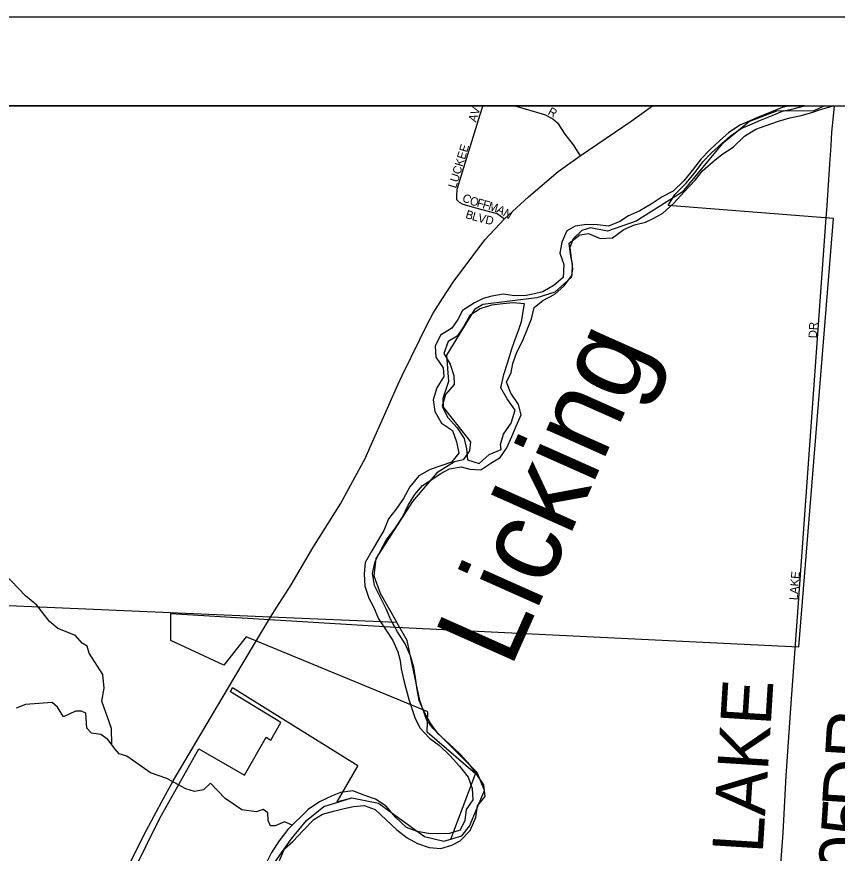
# Model space of a CAD drawing. Extents: x 0 to 40.4, y 0 to 22.
# Drawn here: x 7.886 to 8.807, y 20.061 to 21 of the extents above; entities that cross this region are included whole.
import ezdxf

# ---------------------------------------------------------------- set-up
doc = ezdxf.new("R2010")
doc.units = 0
for name, color, linetype in [('GM_X_City_Street', 7, 'Continuous'), ('GM_X_City_Street_Text', 7, 'Continuous'), ('GM_X_Corporation', 7, 'Continuous'), ('GM_X_County_Road', 7, 'Continuous'), ('GM_X_County_Road_Text', 7, 'Continuous'), ('GM_X_Major_River', 7, 'Continuous'), ('GM_X_Major_River_Text', 7, 'Continuous'), ('GM_X_Minor_River', 7, 'Continuous'), ('GM_X_State_Route', 7, 'Continuous'), ('GM_X_Township', 7, 'Continuous'), ('SH_Data', 7, 'Continuous')]:
    doc.layers.add(name, color=color, linetype=linetype)

msp = doc.modelspace()

# ---------------------------------------------------------------- linework, layer by layer
at = {"layer": 'GM_X_City_Street'}
for points in [[(8.3832, 20.7918), (8.38037, 20.79441), (8.38037, 20.79871), (8.38085, 20.80635), (8.40483, 20.88421), (8.40931, 20.89865), (8.40988, 20.9)], [(8.44554, 20.9), (8.47862, 20.8903), (8.48816, 20.88552), (8.49325, 20.88075), (8.50151, 20.86835), (8.51105, 20.85626), (8.51888, 20.84366)], [(8.3832, 20.7918), (8.38733, 20.78947), (8.40689, 20.78389), (8.42552, 20.77911), (8.43389, 20.77314)], [(8.76279, 20.32617), (8.79491, 20.77428), (8.79587, 20.78799)]]:
    msp.add_lwpolyline(points, dxfattribs=at)
at = {"layer": 'GM_X_Corporation'}
msp.add_line((8.77111, 20.9), (7.12768, 20.9), dxfattribs=at)
msp.add_lwpolyline([(7.92261, 19.84799), (8.04698, 20.10032), (8.09082, 20.17826), (8.14193, 20.14846), (8.16655, 20.19111), (8.17153, 20.188), (8.18298, 20.20784), (8.12643, 20.24202), (8.12866, 20.24682), (8.26913, 20.15958), (8.24575, 20.11864), (8.26251, 20.12298), (8.29252, 20.11699), (8.3443, 20.07961), (8.36594, 20.07446), (8.37365, 20.0767), (8.40118, 20.15007), (8.34715, 20.19685), (8.34786, 20.21962), (8.14411, 20.30392), (8.11903, 20.27206), (8.05953, 20.29981), (8.05953, 20.3301), (8.31154, 20.31467), (8.7642, 20.29247), (8.80299, 20.77365), (8.61749, 20.7881), (8.62503, 20.80048), (8.63741, 20.81279), (8.6471, 20.82437), (8.6569, 20.8375), (8.66611, 20.84703), (8.67779, 20.85753), (8.68707, 20.86603), (8.69941, 20.87434), (8.71196, 20.87985), (8.7214, 20.88397), (8.73425, 20.88923), (8.74605, 20.894), (8.75792, 20.89657), (8.77072, 20.89993), (8.77111, 20.9)], dxfattribs=at)
at = {"layer": 'GM_X_County_Road'}
for points in [[(8.79587, 20.78799), (8.79912, 20.83448), (8.80043, 20.85541), (8.80141, 20.87044), (8.80305, 20.88842), (8.80434, 20.9)], [(8.7332, 19.87386), (8.73264, 19.88464), (8.73362, 19.90129), (8.73684, 19.94579), (8.74104, 20.00863), (8.74663, 20.08391), (8.74999, 20.14786), (8.75545, 20.22385), (8.76279, 20.32617)]]:
    msp.add_lwpolyline(points, dxfattribs=at)
at = {"layer": 'GM_X_Major_River'}
for points in [[(8.75354, 20.9), (8.74557, 20.89827), (8.73343, 20.89337), (8.72053, 20.88809), (8.71104, 20.88394), (8.69815, 20.87828), (8.68524, 20.86959), (8.67574, 20.86089), (8.66397, 20.85031), (8.65447, 20.84048), (8.64458, 20.82724), (8.63508, 20.81589), (8.62331, 20.80417), (8.61078, 20.79775), (8.59864, 20.78944), (8.58573, 20.78226), (8.57321, 20.77661), (8.56334, 20.77018), (8.55082, 20.7649), (8.53832, 20.76644), (8.52581, 20.76684), (8.5133, 20.76497), (8.50382, 20.75968), (8.4981, 20.74681), (8.49617, 20.73469), (8.50069, 20.72181), (8.4999, 20.70741), (8.48965, 20.69872)], [(8.51017, 20.72217), (8.50792, 20.73354), (8.50643, 20.74566), (8.51858, 20.75511), (8.52806, 20.75661), (8.54131, 20.7509), (8.55496, 20.75164), (8.56787, 20.76108), (8.57963, 20.76636), (8.59215, 20.76937), (8.60163, 20.7739), (8.6115, 20.77957), (8.62365, 20.79015), (8.63543, 20.80339), (8.64797, 20.81662), (8.65595, 20.82684), (8.66811, 20.83742), (8.67798, 20.84536), (8.69051, 20.85367), (8.70342, 20.86577), (8.71595, 20.8737), (8.72657, 20.87747), (8.74136, 20.88275), (8.75426, 20.88651), (8.76677, 20.88914), (8.77891, 20.89253), (8.78839, 20.89592), (8.80166, 20.89969), (8.80442, 20.9)], [(8.1815, 20.05264), (8.18683, 20.06589), (8.19633, 20.0742), (8.20849, 20.08668), (8.21989, 20.09878), (8.22975, 20.10483), (8.24189, 20.10821), (8.25402, 20.11122), (8.26426, 20.11348), (8.27639, 20.11459), (8.28889, 20.11002), (8.30099, 20.09826), (8.31309, 20.08725), (8.32482, 20.07814), (8.33617, 20.07168), (8.34943, 20.06748), (8.36231, 20.06632), (8.37483, 20.07009), (8.38431, 20.075), (8.39533, 20.08634), (8.40181, 20.1011), (8.40374, 20.11398), (8.4121, 20.12457), (8.41061, 20.13783), (8.40193, 20.15035), (8.39551, 20.15983), (8.38454, 20.17159), (8.37131, 20.18412), (8.35959, 20.19513), (8.3509, 20.20689), (8.3441, 20.21902), (8.33807, 20.23229), (8.33583, 20.24479), (8.33396, 20.25768), (8.3321, 20.2698), (8.32834, 20.28269), (8.3223, 20.29596), (8.314, 20.30961), (8.30645, 20.32289), (8.30118, 20.3354), (8.29438, 20.34867), (8.28797, 20.36156), (8.28573, 20.37482), (8.28879, 20.38845), (8.29565, 20.40208), (8.30098, 20.4123), (8.31086, 20.42516), (8.31961, 20.43802), (8.32571, 20.45165), (8.33332, 20.46376), (8.34206, 20.47359), (8.35231, 20.48039), (8.3618, 20.48681), (8.37204, 20.49248), (8.38531, 20.49473), (8.39516, 20.49206), (8.40729, 20.49128), (8.41868, 20.49883), (8.42892, 20.50525), (8.43653, 20.51622), (8.44225, 20.52871), (8.44682, 20.54045), (8.45254, 20.55294), (8.44953, 20.56469), (8.44085, 20.57759), (8.43633, 20.58972), (8.44128, 20.60069), (8.4432, 20.61054), (8.44778, 20.62341), (8.45425, 20.6359), (8.45959, 20.64953), (8.46416, 20.66088), (8.46722, 20.67376), (8.4771, 20.68132), (8.49038, 20.68849), (8.50063, 20.69756), (8.50976, 20.71005), (8.51017, 20.72217)], [(8.48965, 20.69872), (8.47712, 20.69117), (8.46764, 20.68891), (8.45816, 20.68703), (8.44527, 20.68668), (8.43239, 20.6886), (8.41988, 20.68635), (8.41002, 20.68371), (8.40015, 20.6788), (8.38687, 20.67011), (8.38154, 20.66028), (8.37469, 20.65044), (8.36217, 20.64251), (8.35607, 20.63002), (8.3568, 20.61789), (8.36511, 20.60576), (8.36585, 20.59628), (8.35786, 20.58342), (8.35404, 20.56979), (8.3559, 20.55691), (8.36307, 20.54363), (8.37556, 20.53566), (8.38008, 20.52277), (8.3827, 20.50988), (8.37434, 20.50005), (8.36258, 20.4959), (8.35044, 20.49176), (8.33791, 20.48458), (8.32765, 20.4721), (8.32042, 20.45923), (8.31205, 20.44675), (8.30369, 20.43616), (8.29835, 20.42329), (8.2915, 20.41118), (8.28503, 20.40058), (8.27742, 20.38734), (8.27625, 20.37446), (8.27698, 20.36082), (8.2815, 20.34718), (8.28678, 20.3377), (8.29243, 20.32405), (8.30074, 20.31153), (8.30867, 20.29977), (8.31433, 20.28688), (8.31696, 20.27741), (8.31807, 20.26793), (8.32069, 20.25619), (8.32333, 20.24633), (8.32708, 20.23231), (8.3331, 20.21336), (8.33876, 20.20161), (8.34972, 20.19022), (8.36107, 20.18187), (8.37279, 20.1701), (8.38338, 20.15872), (8.3932, 20.1462), (8.39772, 20.13369), (8.39845, 20.12081), (8.39084, 20.10984), (8.3893, 20.09772), (8.38434, 20.08674), (8.37221, 20.08297), (8.35856, 20.08262), (8.34871, 20.08302), (8.33583, 20.08531), (8.32409, 20.08988), (8.31161, 20.10127), (8.30103, 20.11379), (8.2893, 20.12176), (8.27718, 20.12557), (8.26354, 20.1309), (8.2499, 20.12903), (8.24041, 20.12526), (8.22637, 20.11847), (8.21347, 20.11016), (8.19068, 20.08747), (8.18117, 20.07499), (8.17242, 20.06175), (8.16633, 20.04964)], [(8.45624, 20.67757), (8.44374, 20.67872), (8.43199, 20.67761), (8.41948, 20.67612), (8.40658, 20.67197), (8.39519, 20.66442), (8.38796, 20.65193), (8.38074, 20.64134), (8.37087, 20.63529), (8.36591, 20.62204), (8.37308, 20.60991), (8.37722, 20.5974), (8.37758, 20.58717), (8.36769, 20.57582), (8.36387, 20.56295), (8.36991, 20.55044), (8.38087, 20.5383), (8.3888, 20.52654), (8.39143, 20.51479), (8.39253, 20.50267), (8.40541, 20.49848), (8.4168, 20.50868), (8.43008, 20.51434)], [(8.43008, 20.51434), (8.42934, 20.51965), (8.43278, 20.53139), (8.44152, 20.54387), (8.44573, 20.55826), (8.43704, 20.57115), (8.42987, 20.58329), (8.43332, 20.59843), (8.43752, 20.61206), (8.44172, 20.62607), (8.44515, 20.63592), (8.44973, 20.64765), (8.45316, 20.65787), (8.45624, 20.67757)]]:
    msp.add_lwpolyline(points, dxfattribs=at)
at = {"layer": 'GM_X_Minor_River'}
for points in [[(7.99318, 20.18271), (7.99297, 20.20087), (7.98194, 20.23156), (7.98458, 20.24635), (7.98305, 20.26151), (7.96787, 20.28537), (7.96559, 20.29333), (7.9599, 20.29673), (7.95231, 20.30544), (7.93259, 20.31338), (7.92311, 20.32095), (7.90907, 20.33951), (7.89618, 20.34973), (7.87227, 20.3751)], [(8.19569, 20.09246), (8.18711, 20.0961), (8.1765, 20.09154), (8.1712, 20.09153), (8.16854, 20.0976), (8.16815, 20.10631), (8.16322, 20.1101), (8.15526, 20.10744), (8.13897, 20.10969), (8.12038, 20.12255), (8.10407, 20.13959), (8.09612, 20.132), (8.08589, 20.13009), (8.07641, 20.13311), (8.05479, 20.14484), (8.0366, 20.15126), (8.01005, 20.1698), (8.00133, 20.17245), (7.99678, 20.17775), (7.98881, 20.18873), (7.98084, 20.19403), (7.97023, 20.19553), (7.9653, 20.20121), (7.96415, 20.21827), (7.95922, 20.22054), (7.95239, 20.22053), (7.93914, 20.21407), (7.9323, 20.22505), (7.92623, 20.22998), (7.89629, 20.22804), (7.88569, 20.22386)]]:
    msp.add_lwpolyline(points, dxfattribs=at)
at = {"layer": 'GM_X_State_Route'}
for points in [[(8.31918, 20.59711), (8.33874, 20.63776), (8.34738, 20.65539), (8.3538, 20.66737), (8.36422, 20.6837), (8.37617, 20.70195), (8.41167, 20.74972), (8.43389, 20.77314), (8.46088, 20.79799), (8.49425, 20.82623), (8.51888, 20.84366), (8.5761, 20.8827), (8.60009, 20.9)], [(8.28291, 20.51601), (8.30124, 20.55717), (8.3142, 20.58678), (8.31918, 20.59711)], [(8.17831, 20.33721), (8.1943, 20.3621), (8.21884, 20.40372), (8.24993, 20.45331), (8.27784, 20.50464), (8.28291, 20.51601)], [(8.1577, 20.30353), (8.17117, 20.32609), (8.17831, 20.33721)], [(7.4592, 19.31877), (7.48215, 19.34054), (7.51327, 19.3667), (7.60128, 19.45473), (7.75209, 19.60989), (7.78934, 19.64799), (7.81474, 19.67424), (7.82772, 19.69004), (7.84094, 19.7099), (7.88176, 19.78841), (7.91834, 19.8609), (8.03221, 20.0867), (8.04878, 20.11833), (8.06193, 20.14225), (8.12997, 20.25714), (8.15432, 20.29786), (8.1577, 20.30353)]]:
    msp.add_lwpolyline(points, dxfattribs=at)
at = {"layer": 'GM_X_Township'}
msp.add_line((8.79303, 20.9), (8.79303, 20.9), dxfattribs=at)
for points in [[(8.79303, 20.9), (8.78122, 20.89419), (8.73935, 20.89384), (8.70881, 20.88235), (8.67774, 20.8568), (8.63347, 20.80287), (8.58179, 20.77068), (8.54934, 20.75921), (8.53035, 20.76319), (8.5208, 20.75986), (8.51082, 20.75083), (8.50731, 20.74098), (8.51013, 20.71701), (8.50889, 20.70714), (8.49047, 20.69097), (8.47024, 20.68432), (8.40967, 20.67693), (8.4001, 20.67132), (8.36879, 20.61992), (8.37118, 20.59063), (8.36453, 20.57131), (8.3652, 20.5618), (8.39566, 20.52273), (8.3948, 20.51285), (8.38748, 20.50266), (8.37794, 20.50047), (8.35804, 20.48812), (8.33072, 20.4557), (8.2894, 20.39185), (8.28731, 20.37249), (8.29436, 20.35303), (8.31323, 20.31996)], [(8.17274, 20.04592), (8.19434, 20.07688), (8.21166, 20.09762), (8.23122, 20.1134), (8.26251, 20.12298), (8.29252, 20.11699), (8.3443, 20.07961), (8.36594, 20.07446), (8.38617, 20.08034), (8.39464, 20.09128), (8.41138, 20.13142), (8.4032, 20.15164), (8.35343, 20.20116), (8.3463, 20.21112), (8.33889, 20.23247), (8.32468, 20.2999), (8.31323, 20.31996), (8.17116, 20.32609), (7.09956, 20.37233)]]:
    msp.add_lwpolyline(points, dxfattribs=at)
at = {"layer": 'SH_Data'}
for p, q in [((2.5, 21), (9.5, 21)), ((2.6, 20.9), (9.4, 20.9))]:
    msp.add_line(p, q, dxfattribs=at)

# ---------------------------------------------------------------- texts
at = {"layer": 'GM_X_City_Street_Text'}
for s, rotation, p in [('V', 72.15955, (8.40448, 20.88888)), ('R', 331.57754, (8.48176, 20.8907)), ('A', 72.18705, (8.40193, 20.88094)), ('LUCKEE', 72.89786, (8.37943, 20.80677)), ('C', 331.93609, (8.38548, 20.79373)), ('O', 344.23866, (8.39416, 20.78937)), ('F', 344.08838, (8.40217, 20.78711)), ('F', 344.13323, (8.40859, 20.78528)), ('M', 343.2013, (8.41497, 20.78347)), ('B', 342.84013, (8.38937, 20.77422)), ('A', 332.71171, (8.42411, 20.78075)), ('N', 328.1892, (8.43135, 20.77703)), ('L', 344.32487, (8.39678, 20.77194)), ('V', 345.85899, (8.40346, 20.77006)), ('D', 347.01914, (8.41174, 20.76798)), ('DR', 86.98901, (8.78447, 20.63883)), ('LAKE', 85.36691, (8.76281, 20.34471))]:
    msp.add_text(s, height=0.00947, rotation=rotation, dxfattribs=at).set_placement(p)
at = {"layer": 'GM_X_County_Road_Text'}
for s, rotation, p in [('LAKE', 86.42245, (8.72369, 20.06002)), ('DR', 86.54661, (8.84695, 20.11036)), ('C-305', 86.18598, (8.83463, 19.91468))]:
    msp.add_text(s, height=0.056818, rotation=rotation, dxfattribs=at).set_placement(p)
at = {"layer": 'GM_X_Major_River_Text'}
msp.add_text('Licking', height=0.094694, rotation=65.99866, dxfattribs=at).set_placement((8.44068, 20.26733))

doc.saveas('drawing.dxf')
